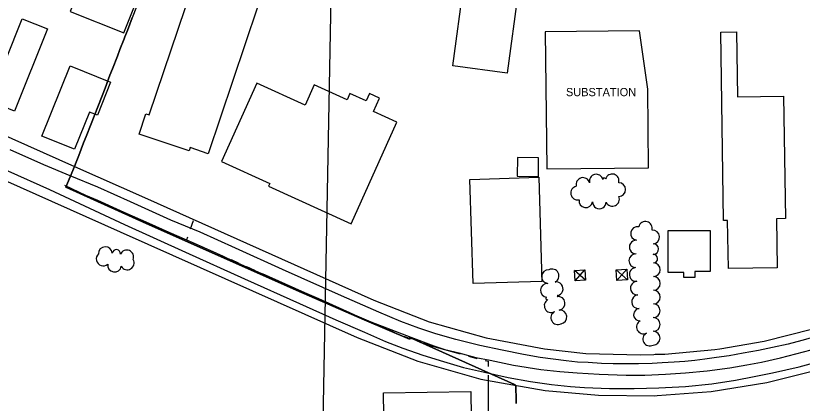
# Model space of a CAD drawing. Extents: x -25029 to 2274964, y -81170 to 687028.
# Drawn here: x -8061 to -6912, y -67010 to -66444 of the extents above; entities that cross this region are included whole.
import ezdxf

# ---------------------------------------------------------------- set-up
doc = ezdxf.new("R2010")
doc.units = 0
for name, color, linetype in [('81911BEA - RW_X_Fee_RW', 7, 'Continuous'), ('BD_X_Canopy', 7, 'Continuous'), ('BLDG', 7, 'Continuous'), ('DIVISIONS', 7, 'Continuous'), ('DV_X_Corp_Line', 7, 'Continuous'), ('GE_X_CL_2000', 7, 'Continuous'), ('ROAD', 7, 'Continuous'), ('TRANSPWRLN', 7, 'Continuous'), ('TREES', 7, 'Continuous')]:
    doc.layers.add(name, color=color, linetype=linetype)

msp = doc.modelspace()

# ---------------------------------------------------------------- linework, layer by layer
at = {"layer": '81911BEA - RW_X_Fee_RW'}
for points in [[(-8389.2, -66545.3), (-8342.6, -66566), (-8278.6, -66594.6), (-7908.5, -66759.7), (-7562.6, -66914)], [(-8249.2, -66542), (-8158.1, -66582.7), (-8066.6, -66623.5), (-7975.3, -66664.2), (-7873, -66709.8), (-7538.1, -66859.2)], [(-7538.1, -66859.2), (-7457.5, -66890.8), (-7374.2, -66914.6), (-7289.1, -66930.6)], [(-7127.2, -66938.4), (-7113.1, -66938.3), (-7040.2, -66931.6), (-7032.7, -66930.3), (-6968.1, -66919.2), (-6897.2, -66901.1), (-6893.1, -66899.7), (-6881, -66895.5), (-6827.9, -66877.4)], [(-7562.6, -66914), (-7473.7, -66948.6), (-7381.9, -66974.5), (-7335, -66982.9), (-7288, -66991.3)], [(-7289.1, -66930.6), (-7228.6, -66937.1), (-7148.5, -66939.4), (-7129.4, -66938.6), (-7127.2, -66938.4)], [(-7288, -66991.3), (-7210.1, -66998.3), (-7127.8, -66999), (-7124.6, -66998.7), (-7045.6, -66992.7), (-6964.3, -66979.7), (-6884.3, -66959.8), (-6806.3, -66933.4)]]:
    msp.add_lwpolyline(points, dxfattribs=at)
at = {"layer": 'BD_X_Canopy'}
for p, q in [((-7594, -66051.8), (-7701.6, -71785.8)), ((-7842.3, -66322.3), (-7890.9, -66447.2)), ((-7842.3, -66322.3), (-7890.9, -66447.2))]:
    msp.add_line(p, q, dxfattribs=at)
at = {"layer": 'BLDG'}
for points in [[(-7893.4, -66274.8), (-7895.1, -66279.2), (-7941.9, -66260.5), (-7940.4, -66256.8), (-7954.8, -66251), (-7978.9, -66311.3), (-7989.5, -66307), (-8014.8, -66370.5), (-8009.6, -66372.6), (-8021.6, -66402.7), (-7975, -66421.3), (-7981.6, -66437.9), (-7903.1, -66469.2), (-7866.5, -66377.5), (-7909.3, -66360.4), (-7877.7, -66281.1)], [(-7352.5, -66405.5), (-7350.4, -66389.4), (-7336.9, -66391.2), (-7339.1, -66407.6), (-7327.6, -66409.1), (-7343.5, -66528), (-7422.9, -66517.4), (-7406.9, -66398.3)], [(-7708, -66431.9), (-7780.1, -66645.7), (-7806.4, -66636.8), (-7808, -66641.7), (-7881, -66617.1), (-7870.9, -66587.3), (-7866, -66588.9), (-7802.4, -66400.1)], [(-8014.8, -66463.5), (-8062.8, -66583.5), (-8099.7, -66568.7), (-8051.7, -66448.8)], [(-7008.4, -66468), (-7007.1, -66562.6), (-6939.7, -66561.6), (-6937.1, -66740.4), (-6950.3, -66740.6), (-6949.2, -66812.4), (-7020.4, -66813.4), (-7021.5, -66742.9), (-7027.4, -66743), (-7031.4, -66468.3)], [(-7922.5, -66541.3), (-7941.9, -66589.5), (-7953.5, -66584.8), (-7975.3, -66639.2), (-8022.9, -66620.1), (-7981.6, -66517.5)], [(-7538.6, -66584.2), (-7529.8, -66564.7), (-7544.4, -66558), (-7549.3, -66568.7), (-7573.1, -66557.9), (-7577.1, -66566.9), (-7625.1, -66545.2), (-7638.4, -66574.7), (-7709, -66542.8), (-7760.7, -66656.9), (-7690.1, -66688.9), (-7692, -66693.2), (-7571.4, -66747.8), (-7504.4, -66599.7)], [(-7328.7, -66678.3), (-7297.9, -66678.7), (-7297.6, -66651.7), (-7328.4, -66651.3)], [(-7297.4, -66680), (-7292.6, -66832.1), (-7393.3, -66835.3), (-7398.1, -66683.1)], [(-7047.2, -66757.5), (-7047.2, -66817.5), (-7069.4, -66817.5), (-7069.4, -66826.3), (-7085.4, -66826.3), (-7085.4, -66818.9), (-7108.2, -66818.9), (-7108.2, -66757.5)], [(-7396.6, -66992.6), (-7394.9, -67105.7), (-7426.4, -67106.2), (-7425.9, -67145.6), (-7392.7, -67145.1), (-7392, -67194.9), (-7521.4, -67158.5), (-7523.8, -66994.5)]]:
    msp.add_lwpolyline(points, close=True, dxfattribs=at)
at = {"layer": 'DIVISIONS'}
for p, q in [((-7802.2, -66743.7), (-7806.2, -66755.6)), ((-7746.7, -66800.2), (-7735.3, -66805.3)), ((-7723.9, -66810.4), (-7712.5, -66815.5)), ((-7701.1, -66820.6), (-7644, -66846.1)), ((-7632.6, -66851.2), (-7621.2, -66856.3)), ((-7609.8, -66861.4), (-7598.4, -66866.5)), ((-7518.4, -66901.9), (-7506.9, -66906.9)), ((-7371, -66968.8), (-7371, -67031.3))]:
    msp.add_line(p, q, dxfattribs=at)
for points in [[(-7810.2, -66767.4), (-7811.5, -66771.3), (-7758.1, -66795.1)], [(-7587, -66871.6), (-7571.1, -66878.7), (-7529.8, -66897)], [(-7495.4, -66911.8), (-7493.4, -66912.6), (-7483.6, -66916)], [(-7471.8, -66920), (-7452.4, -66926.5), (-7411.9, -66937.8)], [(-7399.8, -66941.2), (-7389.3, -66944.1), (-7387.8, -66944.5)], [(-7375.6, -66947.4), (-7371, -66948.5), (-7371, -66956.3)]]:
    msp.add_lwpolyline(points, dxfattribs=at)
at = {"layer": 'DV_X_Corp_Line'}
for p, q in [((-7890.9, -66447.2), (-7898.1, -66465.9)), ((-7890.9, -66447.2), (-7898.1, -66465.9)), ((-7898.1, -66465.9), (-7890.9, -66447.2)), ((-7898.1, -66465.9), (-7890.9, -66447.2)), ((-7898.1, -66465.9), (-7901.7, -66475.2)), ((-7898.1, -66465.9), (-7901.7, -66475.2)), ((-7901.7, -66475.2), (-7898.1, -66465.9)), ((-7901.7, -66475.2), (-7898.1, -66465.9)), ((-7902.8, -66477.9), (-7909, -66493.8)), ((-7902.8, -66477.9), (-7909, -66493.8)), ((-7909, -66493.8), (-7902.8, -66477.9)), ((-7909, -66493.8), (-7902.8, -66477.9)), ((-7901.7, -66475.2), (-7902.8, -66477.9)), ((-7901.7, -66475.2), (-7902.8, -66477.9)), ((-7902.8, -66477.9), (-7901.7, -66475.2)), ((-7902.8, -66477.9), (-7901.7, -66475.2)), ((-7912.6, -66503.2), (-7919.9, -66521.8)), ((-7912.6, -66503.2), (-7919.9, -66521.8)), ((-7919.9, -66521.8), (-7912.6, -66503.2)), ((-7919.9, -66521.8), (-7912.6, -66503.2)), ((-7909, -66493.8), (-7912.6, -66503.2)), ((-7909, -66493.8), (-7912.6, -66503.2)), ((-7912.6, -66503.2), (-7909, -66493.8)), ((-7912.6, -66503.2), (-7909, -66493.8)), ((-7919.9, -66521.8), (-7923.5, -66531.1)), ((-7919.9, -66521.8), (-7923.5, -66531.1)), ((-7923.5, -66531.1), (-7919.9, -66521.8)), ((-7923.5, -66531.1), (-7919.9, -66521.8)), ((-7923.5, -66531.1), (-7930.7, -66549.8)), ((-7923.5, -66531.1), (-7930.7, -66549.8)), ((-7930.7, -66549.8), (-7923.5, -66531.1)), ((-7930.7, -66549.8), (-7923.5, -66531.1)), ((-7930.7, -66549.8), (-7951, -66601.9)), ((-7930.7, -66549.8), (-7951, -66601.9)), ((-7951, -66601.9), (-7930.7, -66549.8)), ((-7951, -66601.9), (-7930.7, -66549.8)), ((-7951, -66601.9), (-7958.3, -66620.5)), ((-7951, -66601.9), (-7958.3, -66620.5)), ((-7958.3, -66620.5), (-7951, -66601.9)), ((-7958.3, -66620.5), (-7951, -66601.9)), ((-7961.9, -66629.9), (-7969.1, -66648.5)), ((-7961.9, -66629.9), (-7969.1, -66648.5)), ((-7969.1, -66648.5), (-7961.9, -66629.9)), ((-7969.1, -66648.5), (-7961.9, -66629.9)), ((-7958.3, -66620.5), (-7961.9, -66629.9)), ((-7958.3, -66620.5), (-7961.9, -66629.9)), ((-7961.9, -66629.9), (-7958.3, -66620.5)), ((-7961.9, -66629.9), (-7958.3, -66620.5)), ((-7969.1, -66648.5), (-7972.8, -66657.8)), ((-7969.1, -66648.5), (-7972.8, -66657.8)), ((-7972.8, -66657.8), (-7969.1, -66648.5)), ((-7972.8, -66657.8), (-7969.1, -66648.5)), ((-7975.3, -66664.2), (-7988.1, -66694.7)), ((-7975.3, -66664.2), (-7988.1, -66694.7)), ((-7988.1, -66694.7), (-7975.3, -66664.2)), ((-7988.1, -66694.7), (-7975.3, -66664.2)), ((-7972.8, -66657.8), (-7975.3, -66664.2)), ((-7972.8, -66657.8), (-7975.3, -66664.2)), ((-7975.3, -66664.2), (-7972.8, -66657.8)), ((-7975.3, -66664.2), (-7972.8, -66657.8)), ((-7988.1, -66694.7), (-7870.8, -66747.7)), ((-7988.1, -66694.7), (-7870.8, -66747.7)), ((-7870.8, -66747.7), (-7988.1, -66694.7)), ((-7870.8, -66747.7), (-7988.1, -66694.7)), ((-7870.8, -66747.7), (-7814.7, -66772.3)), ((-7870.8, -66747.7), (-7814.7, -66772.3)), ((-7814.7, -66772.3), (-7870.8, -66747.7)), ((-7814.7, -66772.3), (-7870.8, -66747.7)), ((-7814.7, -66772.3), (-7651.5, -66844.6)), ((-7814.7, -66772.3), (-7651.5, -66844.6)), ((-7651.5, -66844.6), (-7814.7, -66772.3)), ((-7651.5, -66844.6), (-7814.7, -66772.3)), ((-7651.5, -66844.6), (-7552.4, -66887.9)), ((-7651.5, -66844.6), (-7552.4, -66887.9)), ((-7552.4, -66887.9), (-7651.5, -66844.6)), ((-7552.4, -66887.9), (-7651.5, -66844.6)), ((-7552.4, -66887.9), (-7486.1, -66916.3)), ((-7552.4, -66887.9), (-7486.1, -66916.3)), ((-7486.1, -66916.3), (-7552.4, -66887.9)), ((-7486.1, -66916.3), (-7552.4, -66887.9)), ((-7486.1, -66916.3), (-7485.8, -66914)), ((-7486.1, -66916.3), (-7485.8, -66914)), ((-7485.8, -66914), (-7486.1, -66916.3)), ((-7485.8, -66914), (-7486.1, -66916.3)), ((-7485.8, -66914), (-7332.8, -66982.3)), ((-7485.8, -66914), (-7332.8, -66982.3)), ((-7332.8, -66982.3), (-7485.8, -66914)), ((-7332.8, -66982.3), (-7485.8, -66914)), ((-7332.8, -66982.3), (-7332.8, -66983.3)), ((-7332.8, -66982.3), (-7332.8, -66983.3)), ((-7332.8, -66983.3), (-7332.8, -66982.3)), ((-7332.8, -66983.3), (-7332.8, -66982.3)), ((-7332.8, -66983.3), (-7330.7, -66983.7)), ((-7332.8, -66983.3), (-7330.7, -66983.7)), ((-7330.7, -66983.7), (-7332.8, -66983.3)), ((-7330.7, -66983.7), (-7332.8, -66983.3)), ((-7330.7, -66983.7), (-7330.6, -66990.1)), ((-7330.7, -66983.7), (-7330.6, -66990.1)), ((-7330.6, -66990.1), (-7330.7, -66983.7)), ((-7330.6, -66990.1), (-7330.7, -66983.7)), ((-7330.6, -66990.1), (-7330.5, -67000.2)), ((-7330.6, -66990.1), (-7330.5, -67000.2)), ((-7330.5, -67000.2), (-7330.6, -66990.1)), ((-7330.5, -67000.2), (-7330.6, -66990.1)), ((-7330.5, -67000.2), (-7330.4, -67010.1)), ((-7330.5, -67000.2), (-7330.4, -67010.1)), ((-7330.4, -67010.1), (-7330.5, -67000.2)), ((-7330.4, -67010.1), (-7330.5, -67000.2))]:
    msp.add_line(p, q, dxfattribs=at)
at = {"layer": 'GE_X_CL_2000'}
for points in [[(-7990, -66691.6), (-7968.4, -66701.9), (-7959.1, -66706), (-7941.9, -66713.4), (-7903.3, -66730.8), (-7866.9, -66746.8), (-7837.3, -66760), (-7800.7, -66776.2), (-7768.1, -66790.9), (-7740.4, -66803.4), (-7694.3, -66824.1), (-7657.3, -66840.5), (-7619, -66857.1), (-7573.7, -66877.6), (-7566.6, -66880.7), (-7542.6, -66890.9), (-7484.3, -66913.6), (-7450.7, -66926.1), (-7434.5, -66931.3), (-7419.9, -66934.8), (-7414.1, -66936.2), (-7389.4, -66942.9), (-7368.1, -66947.1), (-7334.2, -66954.3)], [(-7334.2, -66954.3), (-7294.5, -66960.5), (-7266.5, -66963.7), (-7241.3, -66965.5), (-7209.3, -66967.2), (-7169.5, -66969), (-7142.4, -66969), (-7112, -66967.2), (-7082.8, -66965.7), (-7051.3, -66962.5), (-7018.2, -66958.1), (-6993.2, -66954), (-6972, -66950), (-6944.3, -66943.4), (-6899.3, -66932)]]:
    msp.add_lwpolyline(points, dxfattribs=at)
at = {"layer": 'ROAD'}
for points in [[(-6894.2, -66912.9), (-6913, -66918.5), (-6933, -66923.7), (-6955.8, -66928.5), (-6976.6, -66932.9), (-6999, -66936.9), (-7019, -66940.5), (-7037.8, -66943.3), (-7055, -66945.3), (-7069.4, -66947.3), (-7084.2, -66948.9), (-7099.4, -66950.1), (-7117, -66950.9), (-7131.8, -66951.7), (-7151.8, -66952.1), (-7171.4, -66952.1), (-7188.6, -66952.1), (-7205.8, -66951.7), (-7225, -66950.5), (-7240.6, -66949.7), (-7257.4, -66948.1), (-7276.2, -66945.7), (-7295, -66943.3), (-7319.4, -66938.9), (-7350.6, -66932.5), (-7383.4, -66925.7), (-7418.2, -66916.9), (-7447.4, -66908.5), (-7472.2, -66900.1), (-7498.6, -66890.5), (-7530.6, -66876.9), (-7585.4, -66852.9), (-7671.4, -66814.5), (-7740.2, -66783.3), (-7791.8, -66760.1), (-7834.6, -66742.5), (-7893.4, -66716.1), (-7941, -66694.5), (-7981.4, -66678.1), (-8020.2, -66661.7), (-8069, -66640.1)], [(-8133.8, -66643.3), (-8011.8, -66698.1), (-7902.2, -66748.9), (-7813.4, -66789.3), (-7727, -66828.1), (-7646.6, -66864.5), (-7593.8, -66888.1), (-7551.8, -66906.1), (-7521, -66919.7), (-7495.8, -66929.7), (-7466.6, -66939.7), (-7436.6, -66948.9), (-7407, -66957.7), (-7376.6, -66964.5), (-7341.8, -66972.1), (-7309.4, -66978.1), (-7278.6, -66982.5), (-7251, -66985.3), (-7230.6, -66986.9), (-7194.2, -66988.5), (-7158.2, -66988.5), (-7121.8, -66987.3), (-7083, -66985.3), (-7044.6, -66981.3), (-7009.8, -66976.1), (-6982.6, -66970.9), (-6955.8, -66965.3), (-6917, -66956.5), (-6895.8, -66950.9)]]:
    msp.add_lwpolyline(points, dxfattribs=at)
at = {"layer": 'TRANSPWRLN'}
for p, q in [((-7183.2, -66830.5), (-7168.8, -66814)), ((-7228.8, -66830.1), (-7245.1, -66816.2)), ((-7244, -66831.3), (-7230, -66814.9)), ((-7167.8, -66829.5), (-7184.1, -66815.2))]:
    msp.add_line(p, q, dxfattribs=at)
msp.add_lwpolyline([(-7287.8, -66467.7), (-7285.4, -66667.7), (-7137, -66666.1), (-7137.8, -66551.3), (-7150.2, -66466.5)], close=True, dxfattribs=at)
for points in [[(-7183.2, -66830.5), (-7184.1, -66815.2), (-7168.8, -66814), (-7167.8, -66829.5), (-7183.2, -66830.5)], [(-7244, -66831.3), (-7245.1, -66816.2), (-7230, -66814.9), (-7228.8, -66830.1), (-7244, -66831.3)]]:
    msp.add_lwpolyline(points, dxfattribs=at)
at = {"layer": 'TREES'}
for centre, radius, start, end in [((-7213.4, -66685.7), 10, 13.151, 193.151), ((-7190.1, -66685.3), 10, 344.0546, 164.0546), ((-7232.8, -66690.6), 10, 15.3486, 195.3486), ((-7201.7, -66683), 2.03, 13.151, 193.1509), ((-7180.5, -66698), 10, 270.0113, 90.0113), ((-7240.5, -66703.1), 10, 101.4484, 281.4484), ((-7189.6, -66712.2), 10, 204.5096, 24.5096), ((-7228.6, -66714.4), 10, 171.4606, 351.4606), ((-7208.7, -66716.1), 10, 178.6999, 358.6999), ((-7141.5, -66754.7), 10, 345.9846, 165.9846), ((-7153, -66762.1), 10, 80.1067, 260.1067), ((-7131.1, -66767.1), 10, 274.0933, 94.0933), ((-7155, -66781.9), 10, 88.1612, 268.1612), ((-7130.2, -66784.8), 7.75, 271.322, 91.322), ((-7930.2, -66791.4), 10, 2.7429, 182.7429), ((-7914.2, -66791.7), 6.06, 352.592, 172.592), ((-7898.9, -66796.3), 10, 338.0255, 158.0255), ((-7933.4, -66799.3), 10, 132.2644, 312.2644), ((-7898.3, -66805), 10, 209.8125, 29.8125), ((-7155.6, -66801.9), 10, 88.1945, 268.1945), ((-7129.9, -66798.7), 6.2, 271.322, 91.322), ((-7916.8, -66808.3), 10, 170.7014, 350.7014), ((-7277.8, -66824), 10, 297.1168, 117.1168), ((-7155, -66821.9), 10, 95.1204, 275.1204), ((-7129.8, -66814.9), 10, 269.8084, 89.8084), ((-7283.2, -66825), 10, 85.1286, 265.1286), ((-7129.9, -66834.9), 10, 269.8084, 89.8084), ((-7284.9, -66845), 10, 85.1286, 265.1286), ((-7271.8, -66842.8), 10, 278.0216, 98.0216), ((-7153.3, -66841.8), 10, 95.1204, 275.1204), ((-7129.9, -66854.9), 10, 269.8084, 89.8084), ((-7279.2, -66867.4), 10, 118.6123, 298.6123), ((-7284.9, -66856.8), 2.06, 115.1775, 295.1775), ((-7270.4, -66853.4), 0.739, 277.7739, 97.7739), ((-7268.9, -66864), 10, 277.7739, 97.7739), ((-7151.5, -66861.7), 10, 95.1204, 275.1204), ((-7149.8, -66880.6), 8.97, 95.1204, 275.1204), ((-7130, -66874.9), 10, 269.8084, 89.8084), ((-7269.6, -66885), 10, 118.6248, 298.6248), ((-7266.2, -66883.9), 10, 277.7739, 97.7739), ((-7144.5, -66898.5), 10, 116.6198, 296.6198), ((-7130.1, -66894.9), 10, 269.8084, 89.8084), ((-7130.2, -66914.9), 10, 269.337, 89.337), ((-7135.2, -66916.2), 10, 119.0158, 299.0158)]:
    msp.add_arc(centre, radius, start, end, dxfattribs=at)

# ---------------------------------------------------------------- texts
at = {"layer": 'TRANSPWRLN'}
msp.add_text('SUBSTATION', height=12, dxfattribs=at).set_placement((-7257.6, -66561.7))

doc.saveas('drawing.dxf')
